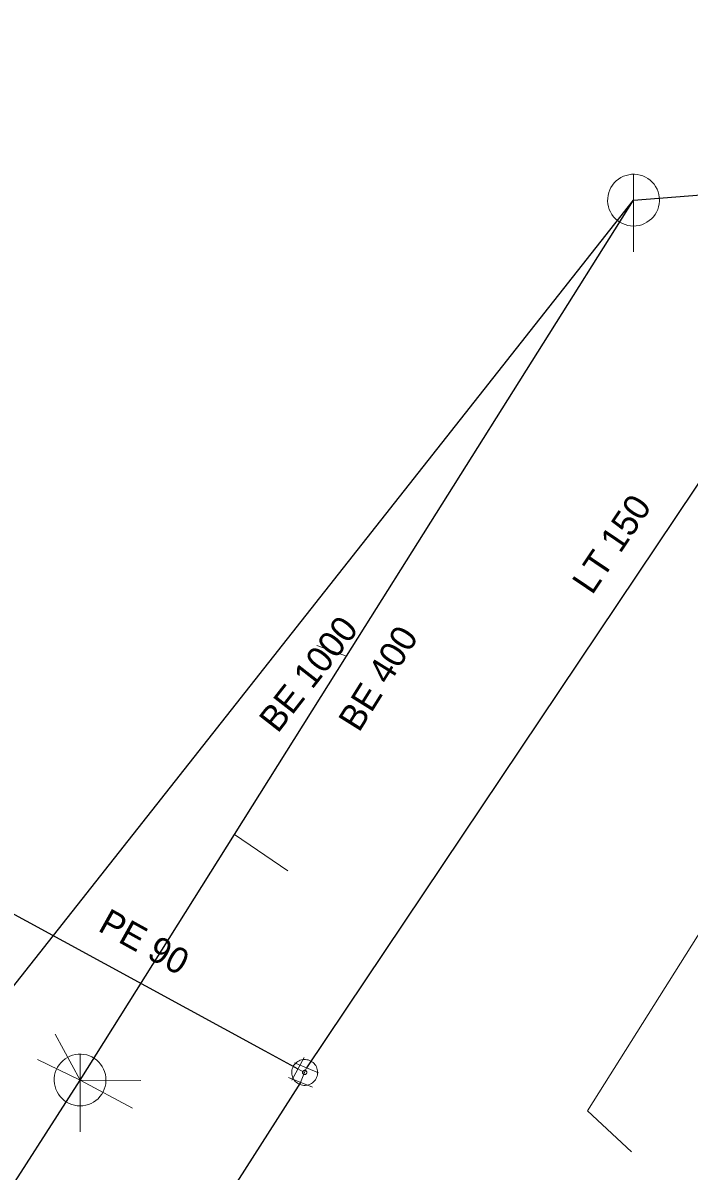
# Model space of a CAD drawing. Extents: x -791337 to -790755, y -988454 to -987923.
# Drawn here: x -791196.42 to -791170.72, y -988016.22 to -987971.9 of the extents above; entities that cross this region are included whole.
import ezdxf

# ---------------------------------------------------------------- set-up
doc = ezdxf.new("R2010")
doc.units = 0
doc.header["$LTSCALE"] = 0.4
for name, color, linetype, lineweight in [('1', 7, 'Continuous', 13), ('11', 7, 'Continuous', 13), ('14', 7, 'Continuous', 25), ('17', 7, 'Continuous', 25), ('22', 7, 'Continuous', 13), ('34', 7, 'Continuous', 13), ('47', 7, 'Continuous', 13)]:
    doc.layers.add(name, color=color, linetype=linetype, lineweight=lineweight)

msp = doc.modelspace()

# ---------------------------------------------------------------- linework, layer by layer
at = {"layer": '11'}
for p, q in [((-791185.079, -987995.928), (-791183.931, -987996.348)), ((-791186.207, -988004.628), (-791188.26, -988003.232)), ((-791195.183, -988010.943), (-791194.219, -988012.71)), ((-791195.861, -988011.914), (-791194.219, -988012.71)), ((-791192.201, -988013.793), (-791194.219, -988012.71)), ((-791191.87, -988012.732), (-791194.219, -988012.71))]:
    msp.add_line(p, q, dxfattribs=at)
msp.add_lwpolyline([(-791172.932, -988015.487), (-791174.64, -988013.903), (-791166.588, -988001.112)], dxfattribs=at)
at = {"layer": '14'}
msp.add_line((-791199.109, -988012.02), (-791172.86, -987978.739), dxfattribs=at)
at = {"layer": '14', "lineweight": 13}
msp.add_line((-791185.552, -988012.418), (-791185.809, -988012.28), dxfattribs=at)
at = {"layer": '14'}
for points in [[(-791194.219, -988012.71), (-791188.26, -988003.232), (-791183.931, -987996.348), (-791172.86, -987978.739), (-791151.633, -987977.064)], [(-791220.36, -988053.399), (-791218.616, -988050.685), (-791216.914, -988048.035), (-791206.587, -988031.96), (-791205.24, -988029.863), (-791199.047, -988020.224), (-791197.614, -988017.994), (-791194.219, -988012.71)]]:
    msp.add_lwpolyline(points, dxfattribs=at)
at = {"layer": '14', "lineweight": 13}
msp.add_lwpolyline([(-791185.71, -988012.8), (-791185.552, -988012.418), (-791185.48, -988012.239)], dxfattribs=at)
at = {"layer": '17'}
msp.add_line((-791158.459, -987971.898), (-791185.48, -988012.239), dxfattribs=at)
for points in [[(-791197.89, -988005.699), (-791187.09, -988011.59), (-791185.809, -988012.28)], [(-791185.71, -988012.8), (-791199.495, -988034.364), (-791203.749, -988041.021), (-791211.533, -988053.348), (-791221.416, -988069.009), (-791228.785, -988080.667), (-791231.254, -988084.482), (-791262.91, -988133.899)]]:
    msp.add_lwpolyline(points, dxfattribs=at)
at = {"layer": '22'}
for p, q in [((-791172.86, -987980.739), (-791172.859, -987977.739)), ((-791194.219, -988014.71), (-791194.218, -988011.71))]:
    msp.add_line(p, q, dxfattribs=at)
for points in [[(-791171.86, -987978.739), (-791171.865, -987978.63), (-791171.883, -987978.522), (-791171.913, -987978.416), (-791171.953, -987978.315), (-791172.005, -987978.218), (-791172.067, -987978.128), (-791172.139, -987978.045), (-791172.219, -987977.971), (-791172.307, -987977.905), (-791172.401, -987977.85), (-791172.501, -987977.805), (-791172.606, -987977.772), (-791172.713, -987977.75), (-791172.822, -987977.74), (-791172.932, -987977.742), (-791173.04, -987977.756), (-791173.147, -987977.781), (-791173.25, -987977.818), (-791173.348, -987977.867), (-791173.44, -987977.925), (-791173.526, -987977.994), (-791173.603, -987978.071), (-791173.672, -987978.157), (-791173.731, -987978.249), (-791173.779, -987978.347), (-791173.816, -987978.45), (-791173.842, -987978.557), (-791173.856, -987978.665), (-791173.859, -987978.775), (-791173.849, -987978.884), (-791173.828, -987978.991), (-791173.794, -987979.095), (-791173.75, -987979.195), (-791173.695, -987979.29), (-791173.629, -987979.378), (-791173.555, -987979.458), (-791173.472, -987979.53), (-791173.382, -987979.592), (-791173.286, -987979.644), (-791173.184, -987979.685), (-791173.079, -987979.715), (-791172.971, -987979.733), (-791172.861, -987979.739), (-791172.752, -987979.733), (-791172.644, -987979.715), (-791172.539, -987979.686), (-791172.437, -987979.645), (-791172.34, -987979.593), (-791172.25, -987979.531), (-791172.167, -987979.46), (-791172.092, -987979.38), (-791172.027, -987979.292), (-791171.971, -987979.198), (-791171.927, -987979.098), (-791171.893, -987978.994), (-791171.871, -987978.886), (-791171.861, -987978.777)], [(-791193.219, -988012.71), (-791193.224, -988012.601), (-791193.242, -988012.493), (-791193.272, -988012.387), (-791193.312, -988012.286), (-791193.364, -988012.189), (-791193.426, -988012.099), (-791193.498, -988012.016), (-791193.578, -988011.942), (-791193.666, -988011.876), (-791193.76, -988011.821), (-791193.86, -988011.776), (-791193.965, -988011.743), (-791194.072, -988011.721), (-791194.181, -988011.711), (-791194.291, -988011.713), (-791194.399, -988011.727), (-791194.506, -988011.752), (-791194.609, -988011.789), (-791194.707, -988011.838), (-791194.799, -988011.896), (-791194.885, -988011.965), (-791194.962, -988012.042), (-791195.031, -988012.128), (-791195.09, -988012.22), (-791195.138, -988012.318), (-791195.175, -988012.421), (-791195.201, -988012.528), (-791195.215, -988012.636), (-791195.218, -988012.746), (-791195.208, -988012.855), (-791195.187, -988012.962), (-791195.153, -988013.066), (-791195.109, -988013.166), (-791195.054, -988013.261), (-791194.988, -988013.349), (-791194.914, -988013.429), (-791194.831, -988013.501), (-791194.741, -988013.563), (-791194.645, -988013.615), (-791194.543, -988013.656), (-791194.438, -988013.686), (-791194.33, -988013.704), (-791194.22, -988013.71), (-791194.111, -988013.704), (-791194.003, -988013.686), (-791193.898, -988013.657), (-791193.796, -988013.616), (-791193.699, -988013.564), (-791193.609, -988013.502), (-791193.526, -988013.431), (-791193.451, -988013.351), (-791193.386, -988013.263), (-791193.33, -988013.169), (-791193.286, -988013.069), (-791193.252, -988012.965), (-791193.23, -988012.857), (-791193.22, -988012.748)]]:
    msp.add_lwpolyline(points, close=True, dxfattribs=at)
at = {"layer": '34'}
for p, q in [((-791185.572, -988011.839), (-791186.046, -988012.719)), ((-791185.942, -988012.049), (-791185.017, -988012.429)), ((-791186.172, -988012.61), (-791185.247, -988012.99))]:
    msp.add_line(p, q, dxfattribs=at)
at = {"layer": '47'}
for points in [[(-791185.992, -988012.181), (-791186.014, -988012.228), (-791186.032, -988012.278), (-791186.043, -988012.328), (-791186.05, -988012.38), (-791186.051, -988012.433), (-791186.047, -988012.485), (-791186.036, -988012.536), (-791186.021, -988012.586), (-791186.002, -988012.634), (-791185.977, -988012.681), (-791185.947, -988012.724), (-791185.912, -988012.763), (-791185.874, -988012.799), (-791185.832, -988012.831), (-791185.788, -988012.858), (-791185.741, -988012.88), (-791185.691, -988012.898), (-791185.64, -988012.909), (-791185.589, -988012.916), (-791185.536, -988012.917), (-791185.484, -988012.913), (-791185.432, -988012.903), (-791185.382, -988012.888), (-791185.334, -988012.868), (-791185.288, -988012.843), (-791185.245, -988012.813), (-791185.205, -988012.778), (-791185.17, -988012.74), (-791185.138, -988012.698), (-791185.111, -988012.654), (-791185.089, -988012.607), (-791185.071, -988012.557), (-791185.059, -988012.506), (-791185.053, -988012.455), (-791185.052, -988012.402), (-791185.056, -988012.35), (-791185.065, -988012.298), (-791185.08, -988012.248), (-791185.101, -988012.2), (-791185.126, -988012.154), (-791185.156, -988012.111), (-791185.19, -988012.071), (-791185.229, -988012.036), (-791185.271, -988012.004), (-791185.315, -988011.977), (-791185.362, -988011.955), (-791185.412, -988011.937), (-791185.462, -988011.925), (-791185.514, -988011.919), (-791185.567, -988011.918), (-791185.619, -988011.922), (-791185.67, -988011.932), (-791185.72, -988011.947), (-791185.768, -988011.967), (-791185.815, -988011.992), (-791185.858, -988012.022), (-791185.897, -988012.056), (-791185.933, -988012.095), (-791185.965, -988012.137)], [(-791185.624, -988012.379), (-791185.628, -988012.387), (-791185.63, -988012.395), (-791185.632, -988012.403), (-791185.633, -988012.411), (-791185.633, -988012.42), (-791185.632, -988012.429), (-791185.631, -988012.437), (-791185.629, -988012.445), (-791185.625, -988012.453), (-791185.621, -988012.461), (-791185.616, -988012.468), (-791185.61, -988012.474), (-791185.604, -988012.48), (-791185.598, -988012.485), (-791185.59, -988012.49), (-791185.582, -988012.494), (-791185.574, -988012.496), (-791185.566, -988012.498), (-791185.558, -988012.499), (-791185.549, -988012.499), (-791185.54, -988012.498), (-791185.532, -988012.497), (-791185.524, -988012.495), (-791185.515, -988012.491), (-791185.508, -988012.487), (-791185.501, -988012.482), (-791185.495, -988012.476), (-791185.489, -988012.47), (-791185.484, -988012.464), (-791185.479, -988012.456), (-791185.475, -988012.448), (-791185.473, -988012.44), (-791185.471, -988012.432), (-791185.47, -988012.424), (-791185.47, -988012.415), (-791185.47, -988012.407), (-791185.472, -988012.398), (-791185.474, -988012.39), (-791185.478, -988012.381), (-791185.482, -988012.374), (-791185.487, -988012.367), (-791185.493, -988012.361), (-791185.499, -988012.355), (-791185.505, -988012.35), (-791185.513, -988012.345), (-791185.521, -988012.341), (-791185.529, -988012.339), (-791185.537, -988012.337), (-791185.545, -988012.336), (-791185.554, -988012.336), (-791185.562, -988012.336), (-791185.571, -988012.338), (-791185.579, -988012.34), (-791185.587, -988012.344), (-791185.595, -988012.348), (-791185.602, -988012.353), (-791185.608, -988012.359), (-791185.614, -988012.365), (-791185.619, -988012.371)]]:
    msp.add_lwpolyline(points, close=True, dxfattribs=at)

# ---------------------------------------------------------------- texts
at = {"layer": '1'}
for s, rotation, p in [('LT 150', 56, (-791174.457, -987994.012)), ('BE 1000 ', 52, (-791186.592, -987999.356)), ('BE 400', 58, (-791183.455, -987999.32)), ('PE 90 ', 331, (-791193.573, -988006.928))]:
    msp.add_text(s, height=1, rotation=rotation, dxfattribs=at).set_placement(p)

doc.saveas('drawing.dxf')
